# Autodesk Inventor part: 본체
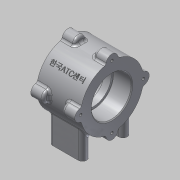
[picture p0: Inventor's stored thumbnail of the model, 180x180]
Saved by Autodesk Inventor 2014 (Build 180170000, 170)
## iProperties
Created: 2015-03
Part Number: 본체
Material: 알루미늄 6061
Document SubType Name: Modeling
Designer: MYHOME
Density: 2.71 g/cm^3
Appearance: 알루미늄 - 평지
Mass: 450.711 g
Surface Area: 331.525 cm^2
Volume: 166.314 cm^3
Author: MYHOME
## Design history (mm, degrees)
sketch "스케치2"
  geometry: C1 r 37 at (0, 0); 1 further point
  constraints: 1 centre point, 1 coincident
  dimensions: "d0" = 74 diameter of C1
extrude "돌출1" new body sketch "스케치2" stored distance "d1" = 52; taper "d2" = 0 deg
node "작업 평면2"
sketch "스케치5"
  geometry: L1 (15, -24)-(-15, -24); L2 (15, -29)-(-15, -29); L3 (-15, -19)-(15, -19); L4 (15, 24)-(-15, 24); L5 (15, 29)-(-15, 29); L6 (-15, 19)-(15, 19); A1 r 5 centre (15, -24) between (15, -29) and (15, -19); A2 r 5 centre (-15, -24) between (-15, -19) and (-15, -29); A3 r 5 centre (15, 24) between (15, 19) and (15, 29); A4 r 5 centre (-15, 24) between (-15, 29) and (-15, 19); 3 further points
  constraints: 16 end point, 8 point on circle, 8 tangent, 4 centre point, 4 parallel, 2 midpoint, 2 vertical alignment, 1 equal radius, 1 horizontal
  dimensions: "d17" = 5 radius of A4; "d18" = 48 distance of L4.start L1.start; "d19" = 40 dimension on A3 A4; "d20" = 24 distance of point (0, 0) point (0, -24)
extrude "돌출3" join sketch "스케치5" stored distance "d21" = 15; taper "d22" = 0 deg
sketch "스케치6"
  geometry: C1 r 23.5 at (0, 0); A1 r 37 centre (0, 0) between (0, 37) and (0, 37) reference
  constraints: 1 centre point, 1 coincident
  dimensions: "d23" = 47 diameter of C1
extrude "돌출4" cut sketch "스케치6" distance "d24" = 22; taper "d25" = 0 deg
hole "구멍2" diameter "d29" = 42; stored, may be unused: countersink angle "d33" = 90 deg, drill point angle "d35" = 0 deg; dims "d27" = 10, "d28" = 10, "d30" = 8, "d31" = 47, "d32" = 22, "d34" = 30
fillet "모깎기1" dims "d36" = 0.3
sketch "스케치8"
  geometry: L1 (0, 0)-(-37.594, 0); L2 (0, 0)-(-26.163, 26.163); A1 r 37 centre (0, 0) between (37, 0) and (37, 0) reference; 4 further points
  constraints: 4 end point, 1 coincident, 1 horizontal, 1 point on circle
  dimensions: "d37" = 45 deg angle of L1 L2
sketch "스케치10"
  geometry: A1 r 5 centre (15, -24) between (15, -29) and (15, -19) reference; A2 r 5 centre (-15, -24) between (-15, -19) and (-15, -29) reference; A3 r 5 centre (-15, 24) between (-15, 29) and (-15, 19) reference; A4 r 5 centre (15, 24) between (15, 19) and (15, 29) reference; 5 further points
  constraints: 4 coincident
hole "구멍3" sketch "스케치10" at (-15, 24), (15, 24), (15, -24), (-15, -24) diameter "d40" = 4.134; stored, may be unused: countersink angle "d44" = 90 deg, drill point angle "d46" = 118 deg; dims "d41" = 6, "d42" = 47, "d43" = 22, "d45" = 8
chamfer "모따기1" distance "d47" = 1; stored, may be unused: second distance "d48" = 2, angle "d49" = 45 deg
fillet "모깎기4" dims "d52" = 3
sketch "스케치11"
  geometry: C1 r 7 at (-37, 0); C2 r 7 at (0, -37); C3 r 7 at (37, 0); C4 r 7 at (0, 37); A1 r 37 centre (0, 0) between (-37, 0) and (0, -37) reference
  constraints: 4 centre point, 4 point on circle, 2 horizontal alignment, 2 vertical alignment
  dimensions: "d55" = 7 radius of C1; "d56" = 7 radius of C2; "d57" = 7 radius of C3; "d58" = 7 radius of C4
extrude "돌출5" join sketch "스케치11" distance "d59" = 15; taper "d60" = 0 deg
sketch "스케치12"
  geometry: A1 r 7 centre (-37, 0) between (-36.338, 6.969) and (-36.338, -6.969) reference; A2 r 7 centre (0, -37) between (-6.969, -36.338) and (6.969, -36.338) reference; A3 r 7 centre (37, 0) between (36.338, -6.969) and (36.338, 6.969) reference; A4 r 7 centre (0, 37) between (6.969, 36.338) and (-6.969, 36.338) reference; 4 further points
  constraints: 4 coincident
hole "구멍4" sketch "스케치12" at (0, 37), (-37, 0), (0, -37), (37, 0) diameter "d61" = 3.242; stored, may be unused: countersink angle "d65" = 90 deg, drill point angle "d67" = 118 deg; dims "d62" = 8, "d63" = 4, "d64" = 2, "d66" = 11
fillet "모깎기5" dims "d68" = 3
fillet "모깎기6" dims "d69" = 3
node "작업 평면4"
sketch "스케치13"
  geometry: 3 further points
  constraints: 1 coincident, 1 other
feature "엠보싱2" sketch "스케치13" dims "d70" = 0.5, "d71" = 0
node "솔리드1"
mirror "대칭2"
other parameters: "d16" = -56
